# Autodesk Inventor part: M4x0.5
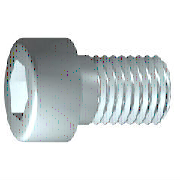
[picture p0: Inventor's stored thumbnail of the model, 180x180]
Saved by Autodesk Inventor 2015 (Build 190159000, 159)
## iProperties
IsCustomPart: 1
Company: 한국ATC센터
Created: 2009-02
Part Number: M4x0.5
Material: Steel, Mild
Description: 6각머리 태핑 나사
Document SubType Name: Modeling
Standard: KS B 1003
Designer: KYOUNG IL JANG
Standards Organization: KS
Language: ko-KR
Size Designation: M 4 x 12
Categories: <MemberInstance><Categories><Category DisplayName="조임쇠" InternalName="e4da775c-781d-43d5-af7c-5136215cf5a6" Mnemonic="FSTN"><Category DisplayName="볼트" InternalN
Density: 1 g/cm^3
Appearance: Steel
Author: KYOUNG IL JANG
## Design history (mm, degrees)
revolve "본체" stored, may be unused: angle "d10" = 90 deg
sketch "스케치2"
  geometry: L1 (0, -4.9)-(0, 4.9) reference; L2 (-4.9, 0)-(4.9, 0) reference; L3 (1.732, 0)-(0.866, -1.5); L4 (0.866, -1.5)-(-0.866, -1.5); L5 (-0.866, -1.5)-(-1.732, 0); L6 (-1.732, 0)-(-0.866, 1.5); L7 (-0.866, 1.5)-(0.866, 1.5); L8 (0.866, 1.5)-(1.732, 0); 2 further points
  constraints: 12 end point, 1 coincident, 1 horizontal alignment, 1 point on line, 12 other
extrude "슬롯" join sketch "스케치2" stored distance "d11" = 10; taper "d12" = 0 deg
workplane "Work Plane1"
fillet "Fillet2" dims "d30" = 0.1 (= R)
body "Solid1"
fillet "모깎기1" dims "d17" = 0.4 (= RR)
feature "스레드" dims "d13" = 10.25 (= GEL), "d14" = 0
chamfer "모따기1" distance "d15" = 0.42941 (= -0.5 x SPD + 0.5 x GD); stored, may be unused: second distance "d16" = 0.42941 (= GUL), angle "d27" = 45 deg
sketch "스케치1"
  geometry: L1 (-1, 0)-(12, 0); L2 (12, 0)-(12, 2); L3 (12, 2)-(1.75, 2); L4 (1.75, 2)-(1.32, 2); L5 (1.32, 2)-(0, 2); L6 (0, 2)-(0, 3.5); L7 (0, 3.5)-(-4, 3.5); L8 (-4, 3.5)-(-4, 1.732); L9 (-4, 1.732)-(-2, 1.732); L10 (-2, 1.732)-(-1, 0); L11 (-7.2, 0)-(15.2, 0) reference; L12 (0, -0.7)-(0, 4.2) reference; L13 (1.75, 2)-(0, 2)
  constraints: 22 end point, 6 parallel, 2 collinear, 2 perpendicular, 1 horizontal, 1 point on line
  dimensions: "d1" = 10.25 distance from line of L3.end L2 (= GEL); "d2" = 0.42952 distance of L4.end L3.end (computed from GAL); "d3" = 4 distance between parallel lines of L8 L6 (= KOH); "d4" = 2 distance of L8.end L9.end (= INTI); "d5" = 60 deg angle of L10 L1; "d6" = 4 diameter of L3 L1 (= GD); "d7" = 4 diameter of L5 L1 (= BDM); "d8" = 3.4641 diameter of L9 L1 (= 1.1547 x SW); "d9" = 7 diameter of L7 L1 (= KOD); "d26" = 12 distance between parallel lines of L12 L2 (= NLG)
other parameters: "GD" = 4 (= NND) [user parameter; used in 2 equation terms], "NLG" = 12 [user parameter; used in 1 equation term], "GEL" = 10.25 [user parameter; used in 2 equation terms], "KOD" = 7 [user parameter; used in 1 equation term], "KOH" = 4 [user parameter; used in 1 equation term], "INTI" = 2 [user parameter; used in 1 equation term], "GAL" = 0.42941 (= 0.61345 x PTC) [user parameter; used in 1 equation term], "GUL" = 0.42941 (= 0.61345 x PTC) [user parameter; used in 1 equation term], "BDM" = 4 (= NND) [user parameter; used in 1 equation term], "SW" = 3 [user parameter; used in 2 equation terms], "RR" = 0.4 [user parameter; used in 1 equation term], "SPD" = 3.14117 (= NND - 1.2269 x PTC) [user parameter; used in 1 equation term], "d19" = 0, "d28" = 0, "d29" = 0, "R" = 0.1 [user parameter; used in 1 equation term], "PHH" = 0.2 [user parameter], "GD1" = 3.14117 (= THREADDIA - 1.2269 x PTC) [user parameter], "THREADDIA" = 4 [user parameter; used in 1 equation term], "FAWI" = 45 deg [user parameter], "TPU" = 14.28571 (computed from PTC) [user parameter], "PTC" = 0.7 [user parameter; used in 5 equation terms], "NND" = 4 [user parameter; used in 3 equation terms], "TOA" = 30 deg [user parameter], "E0" = 3.465 (= 1.155 x SW) [user parameter]
